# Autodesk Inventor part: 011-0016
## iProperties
Created: 2007-02
Part Number: 011-0016
Document SubType Name: Modeling
Designer: GG5883
Material: 34 Cr Mo 4
Description: Pate d'arc boutement
Stock Number: 11-0016
Checked By: GG5883
Author: GG5883
Revision Number: 00
Title: PATE D'ARC-BOUTEMENT
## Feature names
1. Extrusion1
2. Perçage1 [Hole]
3. Perçage2 [Hole]
4. Chanfrein1 [Chamfer]
